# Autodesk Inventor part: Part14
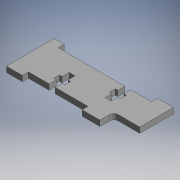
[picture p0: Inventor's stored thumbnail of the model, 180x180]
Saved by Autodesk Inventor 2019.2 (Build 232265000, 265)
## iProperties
Part Number: Part14
Material: Generic
Document SubType Name: Modeling
Designer: richard.girt
Mass: 2.90152 g
Surface Area: 27.0963 cm^2
Volume: 2.90152 cm^3
Density: 1 g/cm^3
Appearance: Default
Author: richard.girt
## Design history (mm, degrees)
sketch "Sketch1"
  geometry: L1 (-30, -12)-(30, -12); L2 (30, -12)-(30, 12); L3 (30, 12)-(-30, 12); L4 (-30, 12)-(-30, -12); L5 (-30, -12)-(30, 12); L6 (30, -12)-(-30, 12); L7 (25, -12)-(-22, -12); L8 (-22, -12)-(-22, -9); L9 (-22, -9)-(25, -9); L10 (25, -9)-(25, -12); L11 (22, 12)-(-8, 12); L12 (-8, 12)-(-8, 9); L13 (-8, 9)-(22, 9); L14 (22, 9)-(22, 12); L15 (-30, 12)-(-17, 12); L16 (-17, 12)-(-17, 7); L17 (-19, 5)-(-30, 5); L18 (-30, 5)-(-30, 12); L19 (11.75, -1)-(8.25, -1); L20 (8.25, -1)-(8.25, 9); L21 (8.25, 9)-(11.75, 9); L22 (11.75, 9)-(11.75, -1); L23 (11.75, -1)-(8.25, 9); L24 (8.25, -1)-(11.75, 9); L25 (12.8, 5.5)-(7.2, 5.5); L26 (7.2, 5.5)-(7.2, 2.5); L27 (7.2, 2.5)-(12.8, 2.5); L28 (12.8, 2.5)-(12.8, 5.5); L29 (12.8, 5.5)-(7.2, 2.5); L30 (7.2, 5.5)-(12.8, 2.5); L31 (-8.25, 1)-(-8.25, -9); L32 (-8.25, -9)-(-11.75, 1); L33 (-11.75, 1)-(-8.25, 1); L34 (-11.75, -9)-(-11.75, 1); L35 (-11.75, -9)-(-8.25, 1); L36 (-8.25, -9)-(-11.75, -9); L37 (-12.8, -5.5)-(-7.2, -5.5); L38 (-12.8, -2.5)-(-12.8, -5.5); L39 (-7.2, -2.5)-(-12.8, -2.5); L40 (-7.2, -2.5)-(-12.8, -5.5); L41 (-12.8, -2.5)-(-7.2, -5.5); L42 (-7.2, -5.5)-(-7.2, -2.5); A1 r 2 centre (-19, 7) between (-19, 5) and (-17, 7); 8 further points
  constraints: 84 end point, 18 parallel, 15 midpoint, 8 horizontal, 8 perpendicular, 4 point on line, 2 point on circle, 2 tangent, 1 centre point
  dimensions: "d0" = 60 distance of L1.start L1.end; "d1" = 24 distance of L1.end L2.end; "d3" = 3 distance of L9.end L7.start; "d4" = 47 distance of L8.end L9.end; "d5" = 8 distance between parallel lines of L2 L14; "d6" = 30 distance between parallel lines of L12 L14; "d7" = 3 distance of L13.end L11.start; "d8" = 7 distance between parallel lines of L3 L17; "d9" = 13 distance between parallel lines of L4 L16; "d10" = 10 distance of L19.end L20.end (= d15); "d12" = 5.6 distance of L25.start L25.end (= d16); "d14" = 20 distance from line of point (10, 9) L2; "d15" = 10 distance of L34.start L32.end; "d16" = 5.6 distance of L39.start L38.start; "d17" = 3.5 distance of L31.end L34.start; "d18" = 20 distance from line of point (-10, -9) L4; "d19" = 2 radius of A1 (derived); "d22" = 9 distance between parallel lines of L12 L16 (derived); "d23" = 8 distance between parallel lines of L4 L8; "d24" = 5 distance between parallel lines of L2 L10 (derived); "d25" = 3 distance of L38.start L37.start
extrude "Extrusion1" new body sketch "Sketch1" stored distance "d20" = 2.8; taper "d21" = 0 deg
body "Solid1"
